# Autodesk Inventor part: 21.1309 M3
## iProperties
Created: 2006-12
Part Number: 21.1309 M3
Document SubType Name: Modeling
Designer: Andy Moles
Material: Steel, Mild
Density: 7.86 g/cm^3
Author: Andy Moles
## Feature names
1. Extrusion1
2. Revolution1
